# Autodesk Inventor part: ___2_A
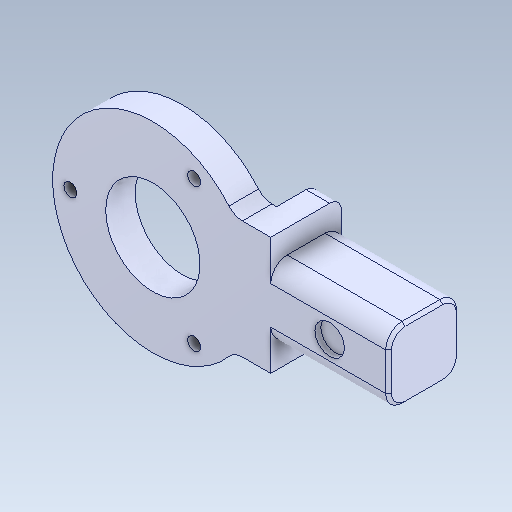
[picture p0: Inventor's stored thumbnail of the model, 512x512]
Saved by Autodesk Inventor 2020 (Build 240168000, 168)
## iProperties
Created: 2017-09
Part Number: ___2_A
Material: Générique
Document SubType Name: Modeling
Designer: bruno
Density: 1 g/cm^3
Appearance: Par défaut
Mass: 7.15765 g
Surface Area: 36.8859 cm^2
Volume: 7.15765 cm^3
Sending System: SolidWorks 2016
Author: bruno
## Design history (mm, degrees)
feature "Importée1"
node "Solide1"
